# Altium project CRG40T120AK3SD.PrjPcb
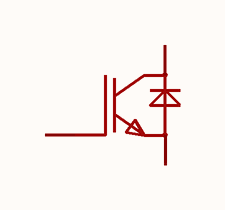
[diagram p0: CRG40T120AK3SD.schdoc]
1 sheet, 1 parts. Net scope: global (net labels, ports and power ports of the same name join across sheets).

## Sheet CRG40T120AK3SD.schdoc
size 127 x 101 mm

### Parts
Q?  crg40t120ak3sd  [TO-247-3_L15.8-W5.0-P5.44-L]  (value not drawn)

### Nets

Not connected (* = marked no-connect by the designer): Q? 1(G) 2(C) 3(E)

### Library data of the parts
Q? = crg40t120ak3sd: IGBT类型:-;耗散功率(Pd):333W;集射极击穿电压(Vces):1.2kV;集电极电流(Ic):40A;; Manufacturer: CRMICRO(华润微); AddInBom: yes; ModelId: 2dc33f6e48bd44aa838c2b9e2b85eb16; ModelTransform: 622.04631,185.078,0,0,0,0,-0.003,13.778,-196.85; Pd - Power Dissipation: 333W; Collector-Emitter Breakdown Voltage (Vces): 1.2kV; Current - Collector(Ic): 40A; Current - Collector Pulsed (Icm): 160A; Vce Saturation(VCE(sat)): 2.4V@10A,15V; Gate-Emitter Threshold Voltage (Vge(th)@Ic): 5V@250uA; Gate Charge(Qg): 208nC@15V; Input Capacitance(Cies): 6.618nF; Output Capacitance(Coes): 131pF; Reverse Transfer Capacitance (Cres): 111pF; Td(on): 77ns; Td(off): 238ns; Turn-On Energy (Eon): 2.8mJ; Switching Energy(Eoff): 1.5mJ; Reverse Recovery Time(trr): 88ns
